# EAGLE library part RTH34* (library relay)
Power PCB Relay 105°C 16A SCHRACK 1 pole 16 A, high-temperature version Source: http://www.schrack.com/.. 5831.pdf
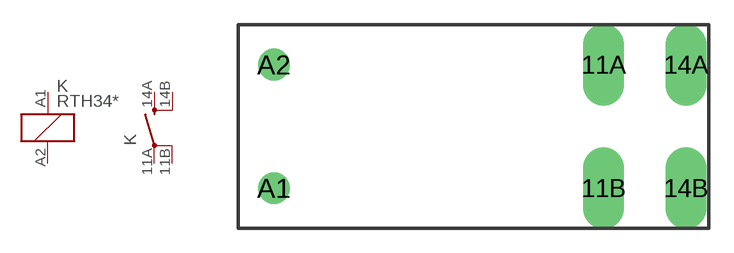
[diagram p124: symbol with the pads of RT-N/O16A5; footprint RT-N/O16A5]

Designator prefix K; gates 1=K 2=S-X2

## RTH34009 (OC_FARNELL: unknown; OC_NEWARK: unknown), RTH34012 (MPN: RTH34012; OC_FARNELL: unknown; OC_NEWARK: 45K1533), RTH34024 (MPN: RTH34024; OC_FARNELL: unknown; OC_NEWARK: 45K1534)  [RT-N/O16A5]
11A  2:PA  pas
11B  2:PB  pas
14A  2:SA  pas
14B  2:SB  pas
A1  1:1  pas
A2  1:2  pas

## Footprint RT-N/O16A5 (pad centres in mm)
Power PCB Relay 1 pole 12 / 16 A, DC- or AC-coil SCHRACK 16 A, pinning 5mm Source: http://www.schrack.com/.. 5819.pdf
drill 1.3 pad 2.5 long: 11A 7.56,3.78; 11B 7.56,-3.78; 14A 12.6,3.78; 14B 12.6,-3.78
drill 1.3 round: A1 -12.6,-3.78; A2 -12.6,3.78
